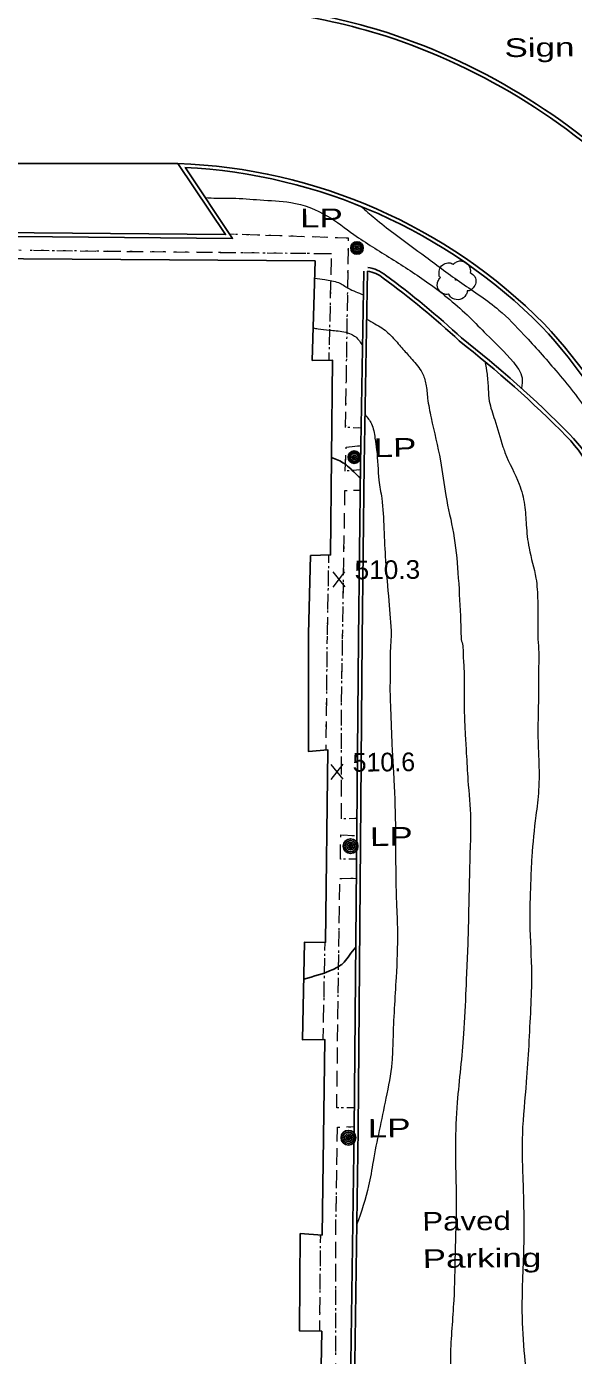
# Model space of a CAD drawing. Extents: x 2362213 to 2366494, y 6968794 to 6978110.
# Drawn here: x 2364072.1 to 2364212.6, y 6975474.3 to 6975816.2 of the extents above; entities that cross this region are included whole.
import ezdxf

# ---------------------------------------------------------------- set-up
doc = ezdxf.new("R2010")
doc.units = 0
doc.header["$LTSCALE"] = 1.9
doc.linetypes.add('DASH_DOUBLE_DOT', pattern=[9.2, 5, -1.2, 0.3, -1.2, 0.3, -1.2])
doc.linetypes.add('DOTTED', pattern=[1.5, 0.3, -1.2])
for name, color, linetype, lineweight in [('11', 7, 'Continuous', 25), ('13', 7, 'Continuous', 13), ('2', 7, 'Continuous', 25), ('20', 7, 'Continuous', 25), ('23', 7, 'Continuous', 25), ('25', 7, 'Continuous', 25), ('29', 7, 'Continuous', 13), ('31', 7, 'Continuous', 25), ('35', 7, 'Continuous', 13)]:
    doc.layers.add(name, color=color, linetype=linetype, lineweight=lineweight)

msp = doc.modelspace()

# ---------------------------------------------------------------- linework, layer by layer
at = {"layer": '11'}
for points in [[(2363982.848, 6975662.41), (2363983.886, 6975757.095), (2364146.266, 6975755.911), (2364145.539, 6975730.323), (2364150.759, 6975730.352), (2364150.226, 6975680.264), (2364145.077, 6975680.125), (2364144.59, 6975659.93)], [(2363982.848, 6975662.41), (2363978.601, 6975307.142), (2364140.395, 6975305.463), (2364140.804, 6975330.719), (2364145.825, 6975330.666), (2364146.589, 6975380.696), (2364141.338, 6975380.606), (2364141.712, 6975430.622), (2364147.015, 6975430.402), (2364147.958, 6975480.533), (2364142.276, 6975480.599), (2364142.448, 6975505.642), (2364148.032, 6975505.265), (2364148.793, 6975555.576), (2364143.044, 6975555.461), (2364143.564, 6975580.656), (2364148.896, 6975580.507), (2364149.503, 6975630.145), (2364144.578, 6975629.678), (2364144.59, 6975659.93)]]:
    msp.add_lwpolyline(points, dxfattribs=at)
at = {"layer": '13'}
for p, q in [((2364125.51, 6975762.744), (2364124.349, 6975762.782)), ((2364131.512, 6975762.551), (2364127.51, 6975762.683)), ((2364137.513, 6975762.348), (2364133.513, 6975762.48)), ((2364143.516, 6975762.155), (2364139.514, 6975762.287)), ((2364149.518, 6975761.962), (2364145.517, 6975762.094)), ((2364077.888, 6975758.52), (2364073.886, 6975758.572)), ((2364083.889, 6975758.457), (2364079.888, 6975758.499)), ((2364089.89, 6975758.384), (2364085.889, 6975758.436)), ((2364095.89, 6975758.311), (2364091.889, 6975758.363)), ((2364101.891, 6975758.248), (2364097.89, 6975758.29)), ((2364107.892, 6975758.186), (2364103.892, 6975758.227)), ((2364113.892, 6975758.123), (2364109.893, 6975758.165)), ((2364119.893, 6975758.06), (2364115.892, 6975758.102)), ((2364125.895, 6975757.997), (2364121.894, 6975758.039)), ((2364131.896, 6975757.934), (2364127.895, 6975757.976)), ((2364137.896, 6975757.871), (2364133.896, 6975757.913)), ((2364143.897, 6975757.808), (2364139.896, 6975757.85)), ((2364149.898, 6975757.746), (2364145.898, 6975757.787)), ((2364150.38, 6975752.35), (2364150.472, 6975756.351)), ((2364154.744, 6975755.112), (2364154.806, 6975759.112)), ((2364154.661, 6975749.109), (2364154.713, 6975753.111)), ((2364150.237, 6975746.347), (2364150.329, 6975750.348)), ((2364154.568, 6975743.108), (2364154.63, 6975747.109)), ((2364150.094, 6975740.347), (2364150.186, 6975744.347)), ((2364154.475, 6975737.108), (2364154.537, 6975741.109)), ((2364149.951, 6975734.345), (2364150.043, 6975738.346)), ((2364149.849, 6975730.344), (2364149.9, 6975732.344)), ((2364154.382, 6975731.107), (2364154.444, 6975735.108)), ((2364154.289, 6975725.105), (2364154.351, 6975729.107)), ((2364154.197, 6975719.104), (2364154.258, 6975723.104)), ((2364154.104, 6975713.104), (2364154.166, 6975717.104)), ((2364158.065, 6975712.931), (2364156.065, 6975713.002)), ((2364154, 6975701.951), (2364154.192, 6975705.943)), ((2364157.888, 6975702.148), (2364155.889, 6975701.999)), ((2364156.088, 6975696.921), (2364157.837, 6975696.967)), ((2364153.772, 6975687.039), (2364153.834, 6975691.04)), ((2364153.679, 6975681.037), (2364153.741, 6975685.039)), ((2364149.736, 6975680.249), (2364149.695, 6975678.249)), ((2364153.586, 6975675.036), (2364153.648, 6975679.037)), ((2364149.654, 6975676.249), (2364149.582, 6975672.248)), ((2364149.542, 6975670.248), (2364149.47, 6975666.247)), ((2364153.493, 6975669.036), (2364153.555, 6975673.036)), ((2364153.4, 6975663.035), (2364153.462, 6975667.035)), ((2364149.429, 6975664.247), (2364149.347, 6975660.245)), ((2364153.338, 6975659.033), (2364153.369, 6975661.033)), ((2364149.335, 6975659.405), (2364149.314, 6975657.404)), ((2364153.263, 6975654.392), (2364153.325, 6975658.393)), ((2364149.293, 6975655.404), (2364149.241, 6975651.403)), ((2364153.16, 6975648.392), (2364153.232, 6975652.391)), ((2364149.22, 6975649.403), (2364149.168, 6975645.403)), ((2364153.067, 6975642.39), (2364153.129, 6975646.391)), ((2364149.147, 6975643.403), (2364149.095, 6975639.402)), ((2364149.064, 6975637.401), (2364149.012, 6975633.4)), ((2364153.021, 6975630.388), (2364153.013, 6975634.389)), ((2364148.991, 6975631.4), (2364148.974, 6975630.09)), ((2364153.028, 6975624.389), (2364153.02, 6975628.388)), ((2364153.026, 6975618.389), (2364153.027, 6975622.389)), ((2364153.033, 6975612.388), (2364153.025, 6975616.388)), ((2364157.022, 6975612.426), (2364155.023, 6975612.397)), ((2364156.932, 6975601.975), (2364154.932, 6975601.966)), ((2364152.532, 6975591.492), (2364152.584, 6975595.493)), ((2364153.049, 6975597.048), (2364156.889, 6975597.075)), ((2364152.449, 6975585.491), (2364152.501, 6975589.492)), ((2364152.376, 6975579.49), (2364152.428, 6975583.491)), ((2364148.736, 6975580.515), (2364148.695, 6975578.516)), ((2364148.654, 6975576.515), (2364148.582, 6975572.514)), ((2364152.293, 6975573.489), (2364152.345, 6975577.491)), ((2364152.21, 6975567.488), (2364152.262, 6975571.489)), ((2364148.541, 6975570.513), (2364148.469, 6975566.512)), ((2364148.438, 6975564.512), (2364148.366, 6975560.511)), ((2364152.137, 6975561.487), (2364152.189, 6975565.488)), ((2364148.325, 6975558.511), (2364148.274, 6975555.561)), ((2364152.054, 6975555.487), (2364152.106, 6975559.487)), ((2364151.982, 6975549.485), (2364152.033, 6975553.487)), ((2364151.899, 6975543.484), (2364151.951, 6975547.485)), ((2364156.371, 6975537.996), (2364154.371, 6975538.017)), ((2364154.288, 6975533.106), (2364156.327, 6975533.186)), ((2364151.841, 6975523.302), (2364151.913, 6975527.303)), ((2364151.748, 6975517.301), (2364151.81, 6975521.302)), ((2364151.655, 6975511.3), (2364151.717, 6975515.301)), ((2364147.602, 6975505.291), (2364147.581, 6975503.291)), ((2364151.589, 6975499.299), (2364151.591, 6975503.299)), ((2364147.56, 6975501.291), (2364147.528, 6975497.29)), ((2364151.587, 6975493.299), (2364151.589, 6975497.299)), ((2364147.507, 6975495.29), (2364147.476, 6975491.289)), ((2364147.455, 6975489.289), (2364147.423, 6975485.29)), ((2364151.584, 6975487.298), (2364151.586, 6975491.299)), ((2364147.412, 6975483.288), (2364147.388, 6975480.538)), ((2364151.581, 6975481.298), (2364151.583, 6975485.299)), ((2364151.578, 6975475.298), (2364151.58, 6975479.298))]:
    msp.add_line(p, q, dxfattribs=at)
at = {"layer": '13', "linetype": 'DOTTED'}
for p, q in [((2364149.736, 6975680.249), (2364149.335, 6975659.405)), ((2364149.335, 6975659.405), (2364148.974, 6975630.09)), ((2364148.736, 6975580.515), (2364148.274, 6975555.561)), ((2364147.602, 6975505.291), (2364147.388, 6975480.538))]:
    msp.add_line(p, q, dxfattribs=at)
for points in [[(2364158.065, 6975712.931), (2364154.104, 6975713.064), (2364154.84, 6975761.793), (2364124.349, 6975762.782)], [(2364149.849, 6975730.344), (2364150.508, 6975757.741), (2363985.952, 6975759.604)], [(2364157.888, 6975702.148), (2364153.991, 6975701.851), (2364154.282, 6975707.985), (2364157.988, 6975708.42)], [(2364153.338, 6975659.033), (2364153.918, 6975696.87), (2364157.837, 6975696.967)], [(2364157.022, 6975612.426), (2364153.033, 6975612.378), (2364153.011, 6975638.769), (2364153.338, 6975659.033)], [(2364156.932, 6975601.975), (2364152.762, 6975601.956), (2364152.872, 6975608.226), (2364156.984, 6975608.035)], [(2364156.371, 6975537.996), (2364151.821, 6975538.033), (2364152.599, 6975597.044), (2364156.889, 6975597.075)], [(2364155.336, 6975462.873), (2364151.575, 6975463.057), (2364151.585, 6975507.139), (2364152.008, 6975533.024), (2364156.327, 6975533.186)]]:
    msp.add_lwpolyline(points, dxfattribs=at)
at = {"layer": '13'}
for points in [[(2364154.827, 6975761.113), (2364154.84, 6975761.793), (2364151.519, 6975761.901)], [(2364154.283, 6975707.945), (2364154.282, 6975707.985), (2364157.988, 6975708.42)], [(2364153.865, 6975693.04), (2364153.918, 6975696.87), (2364154.088, 6975696.872)], [(2364153.014, 6975636.389), (2364153.011, 6975638.769), (2364153.036, 6975640.39)], [(2364152.932, 6975601.957), (2364152.762, 6975601.956), (2364152.826, 6975605.786)], [(2364152.866, 6975607.786), (2364152.872, 6975608.226), (2364156.424, 6975608.06)], [(2364152.371, 6975538.028), (2364151.821, 6975538.033), (2364151.868, 6975541.483)], [(2364151.944, 6975529.305), (2364152.008, 6975533.024), (2364152.288, 6975533.037)], [(2364151.592, 6975505.299), (2364151.585, 6975507.139), (2364151.624, 6975509.301)]]:
    msp.add_lwpolyline(points, dxfattribs=at)
at = {"layer": '2'}
for points in [[(2364111.015, 6975781.006), (2364123.26, 6975762.682), (2363985.381, 6975763.908), (2363984.756, 6975757.093)], [(2364112.916, 6975779.884), (2364125.069, 6975761.709), (2363986.261, 6975762.938), (2363985.717, 6975757.002)], [(2364157.433, 6975658.622), (2364157.905, 6975703.528), (2364158.751, 6975753.29)], [(2364158.393, 6975658.611), (2364158.865, 6975703.517), (2364159.711, 6975753.269)], [(2364153.775, 6975330.732), (2364154.525, 6975406.323), (2364156.324, 6975532.437), (2364157.433, 6975658.622)], [(2364154.735, 6975330.721), (2364155.485, 6975406.312), (2364157.284, 6975532.426), (2364158.393, 6975658.611)]]:
    msp.add_lwpolyline(points, dxfattribs=at)
for centre, radius, start, end in [((2364114.751, 6975656.401), 165.019, 72.45902, 92.37199), ((2364114.751, 6975656.401), 165.979, 72.45902, 92.00254), ((2364113.422, 6975658.096), 164.772, 43.90392, 71.83701), ((2364113.422, 6975658.096), 163.812, 43.90392, 71.83701), ((2364105.853, 6975641.318), 139.783, 44.74585, 87.88383), ((2364105.853, 6975641.318), 138.823, 44.74585, 87.15115), ((2364158.791, 6975745.625), 7.699, 49.82071, 83.13645), ((2364158.791, 6975745.625), 8.659, 49.82071, 83.13645), ((2364032.457, 6975572.645), 221.882, 47.17167, 53.71775), ((2364032.457, 6975572.645), 222.842, 47.17167, 53.71775), ((2364111.914, 6975651.94), 127.083, 5.87305, 43.27918), ((2364111.914, 6975651.94), 128.043, 5.87305, 43.27918), ((2364001.889, 6975504.09), 293.936, 44.6836, 51.89153), ((2364001.889, 6975504.09), 294.896, 44.6836, 51.89153), ((2364179.867, 6975681.229), 43.798, 10.28611, 43.62249), ((2364179.867, 6975681.229), 42.838, 10.28611, 43.62249)]:
    msp.add_arc(centre, radius, start, end, dxfattribs=at)
msp.add_spline([(2364111.015, 6975781.006), (2364045.031, 6975780.968), (2363942.485, 6975780.081), (2363879.276, 6975778.74)], degree=3, dxfattribs=at)
at = {"layer": '20'}
for centre, radius in [((2364157.014, 6975759.263), 1.6), ((2364157.014, 6975759.263), 1.3), ((2364157.014, 6975759.263), 1), ((2364157.014, 6975759.263), 0.539), ((2364157.014, 6975759.263), 0.192), ((2364156.317, 6975705.414), 1.6), ((2364156.317, 6975705.414), 1.3), ((2364156.317, 6975705.414), 1), ((2364156.317, 6975705.414), 0.539), ((2364156.317, 6975705.414), 0.192), ((2364155.38, 6975605.33), 1.9), ((2364155.38, 6975605.33), 1.442), ((2364155.38, 6975605.33), 0.973), ((2364155.38, 6975605.33), 0.539), ((2364155.38, 6975605.33), 0.192), ((2364154.824, 6975530.311), 1.9), ((2364154.824, 6975530.311), 1.442), ((2364154.824, 6975530.311), 0.973), ((2364154.824, 6975530.311), 0.539), ((2364154.824, 6975530.311), 0.192)]:
    msp.add_circle(centre, radius, dxfattribs=at)
at = {"layer": '25', "linetype": 'DASH_DOUBLE_DOT'}
msp.add_spline([(2364310.491, 6975656.319), (2364309.315, 6975672.72), (2364298.364, 6975726.467), (2364286.692, 6975764.268), (2364256.739, 6975841.117), (2364237.482, 6975880.675), (2364207.194, 6975936.919), (2364187.287, 6975969.191), (2364152.962, 6976013.656), (2364115.828, 6976058.935), (2364082.642, 6976102.511), (2364057.611, 6976141.394), (2364041.755, 6976162.894), (2364026.344, 6976185.928), (2364018.13, 6976197.872), (2364016.1, 6976205.372), (2364015.847, 6976210.94), (2364013.084, 6976216.455), (2364009.051, 6976219.846), (2363997.967, 6976222.231), (2363988.629, 6976226.282), (2363979.044, 6976231.97), (2363962.438, 6976249.274), (2363954.619, 6976263.83), (2363947.844, 6976280.085), (2363938.606, 6976306.129), (2363935.221, 6976325.478), (2363933.103, 6976340.059), (2363930.105, 6976355.511)], degree=3, dxfattribs=at)
at = {"layer": '29'}
msp.add_circle((2364182.413, 6975751.054), 0.1, dxfattribs=at)
for points in [[(2364178.448, 6975751.627), (2364178.468, 6975751.637), (2364178.387, 6975751.707), (2364178.151, 6975752.334), (2364178.189, 6975753.615), (2364179.077, 6975754.913), (2364180.382, 6975755.396), (2364181.504, 6975755.206), (2364181.735, 6975755.079), (2364181.805, 6975755.079), (2364181.855, 6975755.12), (2364182.202, 6975755.413), (2364183.068, 6975755.861), (2364184.278, 6975755.793), (2364185.393, 6975755.203), (2364186.127, 6975753.78), (2364186.135, 6975752.92)], [(2364186.125, 6975752.94), (2364187.266, 6975751.881), (2364187.551, 6975750.293), (2364186.843, 6975748.966), (2364186.188, 6975748.42), (2364185.52, 6975748.203), (2364185.37, 6975748.192), (2364185.351, 6975748.082), (2364185.03, 6975747.179), (2364183.492, 6975746.014), (2364181.599, 6975746.296), (2364180.7, 6975747.237), (2364180.629, 6975747.367), (2364180.509, 6975747.346), (2364179.298, 6975747.464), (2364178.028, 6975748.462), (2364177.682, 6975750.099), (2364178.053, 6975751.123), (2364178.378, 6975751.566), (2364178.448, 6975751.617)]]:
    msp.add_spline(points, degree=3, dxfattribs=at)
at = {"layer": '31', "lineweight": 13}
for p, q in [((2364153.975, 6975672.029), (2364150.858, 6975675.88)), ((2364150.895, 6975672), (2364153.938, 6975675.909)), ((2364153.476, 6975622.533), (2364150.359, 6975626.383)), ((2364150.396, 6975622.504), (2364153.439, 6975626.412))]:
    msp.add_line(p, q, dxfattribs=at)
at = {"layer": '31'}
for points in [[(2364157.868, 6975700.048), (2364156.94, 6975700.899), (2364153.773, 6975703.769), (2364150.497, 6975705.338)], [(2364156.738, 6975579.322), (2364155.077, 6975577.257), (2364153.754, 6975575.504), (2364150.862, 6975573.616), (2364143.365, 6975571.144)]]:
    msp.add_spline(points, degree=3, dxfattribs=at)
at = {"layer": '35'}
for points in [[(2364072.34, 6976232.799), (2364073.512, 6976229.42), (2364077.259, 6976223.586), (2364080.684, 6976221.048), (2364085.489, 6976219.444), (2364096.529, 6976220.399), (2364104.253, 6976222.263), (2364113.022, 6976225.507), (2364121.237, 6976227.175), (2364127.609, 6976229.046), (2364136.239, 6976232.147), (2364145.642, 6976235.187), (2364157.377, 6976239.82), (2364167.269, 6976242.914), (2364173.419, 6976245.093), (2364177.159, 6976246.138), (2364182.834, 6976247.582), (2364187.288, 6976249.415), (2364190.094, 6976249.852), (2364194.192, 6976252.231), (2364196.76, 6976252.465), (2364198.8, 6976251.425), (2364201.262, 6976250.088), (2364202.078, 6976249.366), (2364205.917, 6976245.342), (2364207.815, 6976241.38), (2364208.182, 6976238.563), (2364208.199, 6976234.632), (2364207.621, 6976227.067), (2364204.466, 6976221.297), (2364195.991, 6976215.556), (2364186.61, 6976211.356), (2364179.997, 6976206.383), (2364177.182, 6976202.777), (2364171.12, 6976194.578), (2364169.564, 6976188.912), (2364167.653, 6976180.585), (2364169.466, 6976177.072), (2364173.6, 6976170.44), (2364175.867, 6976165.441), (2364179.819, 6976155.679), (2364180.418, 6976150.605), (2364181.385, 6976145.683), (2364184.744, 6976136.326), (2364190.308, 6976126.588), (2364191.656, 6976118.44), (2364193.883, 6976113.511), (2364197.092, 6976103.061), (2364197.561, 6976099.005), (2364197.256, 6976093.182), (2364195.64, 6976087.517), (2364190.927, 6976084.662), (2364184.763, 6976085.023), (2364175.902, 6976089.369), (2364170.097, 6976094.053), (2364167.302, 6976094.547), (2364165.792, 6976093.472), (2364166.207, 6976086.627), (2364172.238, 6976076.103), (2364176.702, 6976067.325), (2364183.259, 6976058.097), (2364190.131, 6976047.482), (2364200.603, 6976030.541), (2364208.632, 6976015.918), (2364215.456, 6976004.081), (2364221.311, 6975995.117), (2364229.207, 6975981.811), (2364236.007, 6975972.486), (2364246.472, 6975956.274), (2364257.257, 6975935.896), (2364269.014, 6975914.217), (2364282.116, 6975889.911), (2364298.76, 6975853.857), (2364308.901, 6975829.593), (2364317.772, 6975806.466), (2364324.557, 6975786), (2364331.089, 6975764.871), (2364338.336, 6975738.949), (2364344.181, 6975710.153), (2364349.805, 6975685.556), (2364355.377, 6975654.907)], [(2364338.083, 6975724.585), (2364336.615, 6975724.301), (2364332.897, 6975724.156), (2364330.944, 6975724.427), (2364327.99, 6975725.859), (2364323.306, 6975730.466), (2364319.832, 6975735.023), (2364316.951, 6975741.476), (2364313.477, 6975751.353), (2364308.571, 6975764.477), (2364303.366, 6975780.728), (2364300.847, 6975790.103), (2364295.903, 6975802.078), (2364289.848, 6975815.18), (2364285.058, 6975826.636), (2364283.051, 6975832.687), (2364274.982, 6975849.361), (2364268.092, 6975862.966), (2364261.32, 6975875.742), (2364251.974, 6975895.144), (2364246.937, 6975903.286), (2364237.266, 6975918.085), (2364226.857, 6975933.636), (2364217.746, 6975945.28), (2364207.599, 6975959.514), (2364196.54, 6975974.18), (2364185.616, 6975985.926), (2364174.812, 6975996.945), (2364166.449, 6976005.614), (2364155.588, 6976016.182), (2364145.672, 6976026.137), (2364136.565, 6976037.291), (2364127.736, 6976048.768), (2364120.236, 6976058.047), (2364118.827, 6976059.023), (2364117.4, 6976058.69), (2364116.621, 6976057.522), (2364117.953, 6976052.085), (2364125.267, 6976040.225), (2364131.396, 6976029.912), (2364137.715, 6976020.471), (2364144.074, 6976012.322), (2364149.513, 6976005.123), (2364161.13, 6975988.593), (2364171.865, 6975974.575), (2364183.632, 6975959.016), (2364188.295, 6975950.451), (2364195.177, 6975937.715), (2364197.176, 6975931.494), (2364198.686, 6975924.148), (2364199.903, 6975916.059), (2364201.962, 6975908.868), (2364204.663, 6975896.113), (2364208.746, 6975885.272), (2364208.665, 6975875.87), (2364207.918, 6975871.333), (2364206.096, 6975865.276), (2364198.899, 6975856.667), (2364193.718, 6975854.617), (2364186.334, 6975849.657), (2364176.884, 6975845.466), (2364166.142, 6975838.313), (2364160.356, 6975833.499), (2364152.733, 6975828.676), (2364145.37, 6975827.866), (2364140.008, 6975828.035), (2364131.629, 6975831.065), (2364125.476, 6975837.686)], [(2364331.011, 6975655.455), (2364330.022, 6975659.535), (2364328.67, 6975665.984), (2364325.76, 6975678.626), (2364323.112, 6975694.202), (2364319.538, 6975707.139), (2364314.851, 6975723.604), (2364310.44, 6975741.514), (2364307.149, 6975751.053), (2364303.632, 6975764.44), (2364300.481, 6975777.08), (2364295.15, 6975792.949), (2364291.586, 6975801.747), (2364285.554, 6975814.529), (2364280.358, 6975826.711), (2364273.022, 6975842.992), (2364265.83, 6975857.904), (2364262.28, 6975866.291), (2364253.686, 6975881.319), (2364246.103, 6975893.178), (2364234.291, 6975912.216), (2364226.56, 6975922.773), (2364217.938, 6975932.441), (2364209.664, 6975940.133), (2364202.587, 6975949.286), (2364199.152, 6975953.943), (2364198.588, 6975954.348), (2364197.409, 6975954.327), (2364196.993, 6975953.903), (2364196.858, 6975952.332), (2364198.209, 6975945.854), (2364200.892, 6975937.139), (2364203.554, 6975929.644), (2364204.999, 6975921.808), (2364207.659, 6975909.082), (2364212.238, 6975896.725), (2364219.818, 6975879.897), (2364224.917, 6975867.435), (2364226.429, 6975863.079), (2364229.662, 6975853.159), (2364231.188, 6975848.354), (2364233.261, 6975840.813), (2364234.334, 6975834.183), (2364234.868, 6975828.528), (2364235.385, 6975820.422), (2364235.495, 6975815.212), (2364235.8, 6975805.266), (2364236.124, 6975799.598), (2364236.834, 6975789.034), (2364235.994, 6975783.867), (2364234.598, 6975779.243), (2364233.322, 6975776.711), (2364227.105, 6975777.372)], [(2364118.028, 6975772.232), (2364121.011, 6975772.06), (2364124.981, 6975772.078), (2364132.125, 6975771.626), (2364140.001, 6975770.961), (2364149.466, 6975767.461), (2364156.211, 6975762.726), (2364165.841, 6975756.527), (2364175.472, 6975750.148), (2364185.954, 6975741.418), (2364190.257, 6975737.089), (2364197.226, 6975729.855), (2364199.434, 6975725.855), (2364199.31, 6975723.153)], [(2364158.062, 6975769.953), (2364161.591, 6975766.916), (2364166.479, 6975763.044), (2364174.707, 6975756.952), (2364183.931, 6975750.218), (2364193.508, 6975743.279), (2364199.939, 6975736.901), (2364208.126, 6975727.708), (2364216.675, 6975716.44), (2364222.16, 6975705.41), (2364224.241, 6975698.98), (2364226.228, 6975692.029), (2364227.597, 6975684.782), (2364229.139, 6975670.926), (2364229.756, 6975657.58)], [(2364146.138, 6975751.509), (2364148.751, 6975751.114), (2364152.269, 6975750.337), (2364154.793, 6975748.901), (2364158.649, 6975747.217)], [(2364145.78, 6975738.665), (2364147.002, 6975738.447), (2364149.905, 6975738.135), (2364151.687, 6975737.962), (2364155.515, 6975737.088), (2364156.692, 6975736.369), (2364158.423, 6975734.146)], [(2364159.499, 6975740.966), (2364161.609, 6975739.756), (2364163.43, 6975738.674), (2364166.386, 6975736.002), (2364168.823, 6975733.245), (2364171.188, 6975730.547), (2364173.751, 6975727.16), (2364174.729, 6975724.199), (2364175.183, 6975720.594), (2364176.061, 6975715.583), (2364178.466, 6975704.524), (2364179.852, 6975695.527), (2364181.814, 6975685.886), (2364182.962, 6975675.656), (2364183.587, 6975664.572), (2364183.785, 6975658.523)], [(2364189.884, 6975730.045), (2364190.435, 6975726.789), (2364190.762, 6975722.892), (2364191.032, 6975719.804), (2364192.417, 6975715.068), (2364194.513, 6975708.118), (2364195.027, 6975706.663), (2364198.705, 6975698.457), (2364200.076, 6975693.16), (2364200.525, 6975687.984), (2364201.241, 6975682.05), (2364203.005, 6975674.286), (2364203.471, 6975668.452), (2364203.495, 6975658.57)], [(2364159.083, 6975716.321), (2364160.734, 6975714.027), (2364161.639, 6975710.335), (2364162.068, 6975707.289), (2364162.673, 6975699.474), (2364163.367, 6975694.841), (2364163.942, 6975686.996), (2364164.35, 6975678.819), (2364165.199, 6975668.447), (2364165.843, 6975659.622)], [(2364203.495, 6975658.57), (2364203.718, 6975655.132), (2364203.695, 6975651.262), (2364203.653, 6975644.052), (2364203.531, 6975636.95), (2364203.537, 6975633.15), (2364203.739, 6975627.731), (2364203.695, 6975619.752), (2364202.997, 6975613.184), (2364201.938, 6975602.594), (2364201.634, 6975595.721), (2364201.419, 6975585.687), (2364201.886, 6975572.331), (2364201.63, 6975563.578), (2364201.15, 6975554.054), (2364200.53, 6975544.667), (2364199.526, 6975531.398), (2364199.632, 6975520.257), (2364199.884, 6975504.319), (2364199.418, 6975487.034), (2364199.918, 6975475.498), (2364201.047, 6975465.088), (2364201.816, 6975455.785), (2364202.839, 6975447.085), (2364203.588, 6975441.891), (2364204.389, 6975433.429), (2364204.668, 6975425.111), (2364204.368, 6975414.588), (2364203.373, 6975406.748), (2364202.679, 6975396.631), (2364201.049, 6975387.195), (2364199.996, 6975379.154), (2364198.698, 6975373.671), (2364197.072, 6975367.936), (2364194.954, 6975360.436), (2364193.75, 6975352.424), (2364191.269, 6975346.23), (2364189.323, 6975340.551), (2364188.402, 6975336.482), (2364184.943, 6975333.109), (2364181.672, 6975330.137), (2364178.842, 6975325.88), (2364175.592, 6975320.609), (2364172.095, 6975317.136), (2364166.605, 6975315.014), (2364161.058, 6975312.581), (2364154.949, 6975310.362), (2364146.011, 6975309.007)], [(2364183.785, 6975658.523), (2364184.19, 6975656.896), (2364184.301, 6975654.747), (2364184.541, 6975650.4), (2364184.588, 6975644.521), (2364184.649, 6975638.08), (2364184.823, 6975634.402), (2364185.122, 6975629.294), (2364185.529, 6975622.239), (2364186.214, 6975612.304), (2364186.163, 6975607.113), (2364185.773, 6975592.479), (2364185.588, 6975583.516), (2364185.002, 6975568.53), (2364184.421, 6975557.044), (2364182.789, 6975539.368), (2364182.305, 6975528.313), (2364182.532, 6975513.834), (2364182.229, 6975500.561), (2364181.884, 6975488.497), (2364181.031, 6975474.088), (2364181.699, 6975455.384), (2364181.973, 6975445.466), (2364182.123, 6975433.947), (2364181.17, 6975419.527), (2364179.877, 6975409.354), (2364177.727, 6975399.933), (2364174.89, 6975390.116), (2364173.482, 6975379.412), (2364172.729, 6975374.434), (2364169.306, 6975367.382), (2364166.814, 6975361.298), (2364164.82, 6975354.328), (2364162.553, 6975341.496), (2364160.105, 6975337.053), (2364154.77, 6975334.342)], [(2364165.843, 6975659.622), (2364165.571, 6975655.649), (2364165.547, 6975649.829), (2364165.495, 6975645.789), (2364165.657, 6975640.33), (2364165.897, 6975634.071), (2364166.152, 6975628.233), (2364166.508, 6975622.398), (2364166.903, 6975609.25), (2364166.936, 6975602.63), (2364167.18, 6975590.702), (2364167.419, 6975583.463), (2364167.062, 6975571.58), (2364166.598, 6975563.555), (2364166.246, 6975555.422), (2364165.971, 6975549.638), (2364164.467, 6975540.493), (2364162.726, 6975532.137), (2364161.153, 6975524.171), (2364160.022, 6975517.97), (2364156.938, 6975507.931)]]:
    msp.add_spline(points, degree=3, dxfattribs=at)

# ---------------------------------------------------------------- texts
at = {"layer": '2'}
for s, width, p in [('Paved', 1.25, (2364173.833, 6975506.381)), ('Parking', 1.4, (2364173.924, 6975496.781))]:
    msp.add_text(s, height=4.8, rotation=0.546, dxfattribs=dict(at, width=width)).set_placement(p)
at = {"layer": '20', "width": 1.4}
for p in [(2364137.423, 6975764.477), (2364156.317, 6975705.413), (2364155.38, 6975605.33), (2364154.824, 6975530.312)]:
    msp.add_text('  LP', height=4.8, rotation=0.546, dxfattribs=at).set_placement(p)
at = {"layer": '23', "width": 1.4}
msp.add_text('Sign', height=4.8, rotation=0.546, dxfattribs=at).set_placement((2364194.948, 6975808.367))
at = {"layer": '31', "width": 1.05}
msp.add_text('510.3', height=4.8, rotation=0.546, dxfattribs=at).set_placement((2364156.416, 6975673.993))
at = {"layer": '31'}
msp.add_text('510.6', height=4.8, rotation=0.546, dxfattribs=at).set_placement((2364155.917, 6975624.497))

doc.saveas('drawing.dxf')
